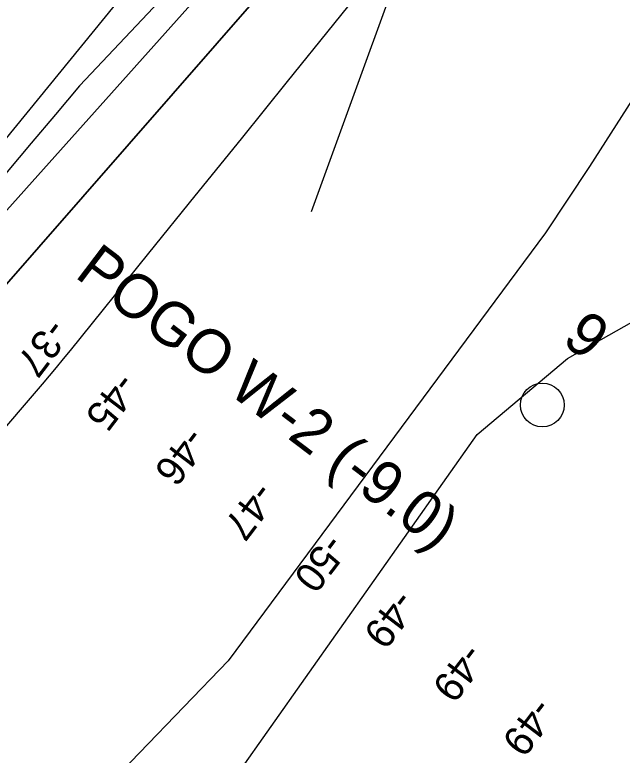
# Model space of a CAD drawing. Extents: x 3913936 to 3933962, y 195330 to 217741.
# Drawn here: x 3922257 to 3922950, y 200928 to 201772 of the extents above; entities that cross this region are included whole.
import ezdxf

# ---------------------------------------------------------------- set-up
doc = ezdxf.new("R2010")
doc.units = 0
for name, color, linetype in [('V-ANNO-TEXT', 7, 'Continuous'), ('V-CHAN-NAID', 7, 'Continuous'), ('V-RIVR-IDEN', 7, 'Continuous'), ('V-RIVR-MILE', 7, 'Continuous'), ('V-RIVR-RANG', 7, 'Continuous'), ('V-TOPO-DPTH', 7, 'Continuous'), ('V-TOPO-MAJR', 7, 'Continuous'), ('V-TOPO-MINR', 7, 'Continuous')]:
    doc.layers.add(name, color=color, linetype=linetype)

msp = doc.modelspace()

# ---------------------------------------------------------------- linework, layer by layer
at = {"layer": 'V-ANNO-TEXT'}
msp.add_lwpolyline([(3923713.15, 204620.63), (3922595.25, 201547.11)], dxfattribs=at)
at = {"layer": 'V-RIVR-MILE'}
msp.add_circle((3922858.84, 201326.88), 25, dxfattribs=at)
at = {"layer": 'V-TOPO-DPTH'}
for points in [[(3923377.96, 202699), (3922941.35, 202158.48), (3922940.31, 202157.2), (3922937.13, 202153.43), (3922933.95, 202149.66), (3922932.91, 202148.38), (3922620.43, 201761.19), (3922567.77, 201695.94), (3922515.1, 201630.7), (3922462.43, 201565.47), (3922409.75, 201500.24), (3922320.06, 201389.21), (3922312.18, 201379.53), (3922304.23, 201369.9), (3922296.21, 201360.34), (3922288.13, 201350.82), (3922167.81, 201210.31), (3922100.01, 201130.19), (3922032.83, 201049.55), (3921966.59, 200968.13), (3921900.98, 200886.2)], [(3923377.96, 202699), (3922941.35, 202158.48), (3922940.31, 202157.2), (3922937.13, 202153.43), (3922933.95, 202149.66), (3922932.91, 202148.38), (3922620.43, 201761.19), (3922567.77, 201695.94), (3922515.1, 201630.7), (3922462.43, 201565.47), (3922409.75, 201500.24), (3922320.06, 201389.21), (3922312.18, 201379.53), (3922304.23, 201369.9), (3922296.21, 201360.34), (3922288.13, 201350.82), (3922167.81, 201210.31), (3922100.01, 201130.19), (3922032.83, 201049.55), (3921966.59, 200968.13), (3921900.98, 200886.2)], [(3923095.91, 202678.46), (3922791.11, 202297.8), (3922789.59, 202295.95), (3922787.26, 202293.23), (3922784.95, 202290.48), (3922157.44, 201521.67), (3922155.7, 201519.54), (3922153.96, 201517.41), (3922152.21, 201515.29), (3922150.47, 201513.16), (3922148.07, 201510.25), (3922146.97, 201508.92), (3922146.42, 201508.26), (3922145.87, 201507.61), (3922141.95, 201502.95), (3922139.44, 201499.96), (3922136.94, 201496.96), (3922134.44, 201493.96), (3922131.96, 201490.95), (3921528.01, 200758.19)], [(3923045.56, 202377.72), (3922233.85, 201449.62), (3922231.73, 201447.13), (3922229.61, 201444.64), (3922227.46, 201442.17), (3922225.3, 201439.71), (3922161.81, 201367.9), (3922127.91, 201329.54), (3922094.02, 201291.17), (3922060.15, 201252.77), (3922026.29, 201214.37), (3921757.53, 200909.33)], [(3921757.53, 200909.33), (3922026.29, 201214.37), (3922060.15, 201252.77), (3922094.02, 201291.17), (3922127.91, 201329.54), (3922161.81, 201367.9), (3922225.3, 201439.71), (3922227.46, 201442.17), (3922229.61, 201444.64), (3922231.73, 201447.13), (3922233.85, 201449.62), (3923045.56, 202377.72)], [(3921571.56, 200731.02), (3921771, 200981.89), (3921838.64, 201066.04), (3921906.88, 201149.7), (3921976, 201232.63), (3922045.72, 201315.07), (3922153.04, 201440.58), (3922169.51, 201459.92), (3922185.93, 201479.31), (3922202.27, 201498.77), (3922970.95, 202357.51)], [(3921571.56, 200731.02), (3921771, 200981.89), (3921838.64, 201066.04), (3921906.88, 201149.7), (3921976, 201232.63), (3922045.72, 201315.07), (3922153.04, 201440.58), (3922169.51, 201459.92), (3922185.93, 201479.31), (3922202.27, 201498.77), (3922970.95, 202357.51)]]:
    msp.add_lwpolyline(points, dxfattribs=at)
at = {"layer": 'V-TOPO-MAJR'}
for points in [[(3922784.7, 201293.34), (3922887.7, 201379.88), (3923450.03, 201697.58)], [(3922961.24, 201675.14), (3922912.58, 201598.93), (3922862.65, 201523.49), (3922500.28, 201035.07)], [(3921323.53, 199362.66), (3921429.11, 199484.6), (3921440.3, 199497.41), (3921451.56, 199510.15), (3921462.94, 199522.78), (3921474.4, 199535.35), (3921526.44, 199591.94), (3921563.74, 199632.96), (3921600.74, 199674.25), (3921637.27, 199715.94), (3921673.5, 199757.91), (3922047.51, 200196.03), (3922076.19, 200231.14), (3922103.81, 200267.04), (3922129.84, 200304.1), (3922154.82, 200341.94), (3922334.63, 200627.7), (3922384.43, 200710.11), (3922432.18, 200793.65), (3922784.7, 201293.34)], [(3922500.28, 201035.07), (3922247.49, 200772.95), (3922181.56, 200701.24), (3922117.29, 200628.04), (3922054.13, 200553.84), (3921951.57, 200430.5), (3921940.66, 200417.11), (3921929.94, 200403.57)]]:
    msp.add_lwpolyline(points, dxfattribs=at)
at = {"layer": 'V-TOPO-MINR'}
for points in [[(3923377.96, 202699), (3922941.35, 202158.48), (3922940.31, 202157.2), (3922937.13, 202153.43), (3922933.95, 202149.66), (3922932.91, 202148.38), (3922620.43, 201761.19), (3922567.77, 201695.94), (3922515.1, 201630.7), (3922462.43, 201565.47), (3922409.75, 201500.24), (3922320.06, 201389.21), (3922312.18, 201379.53), (3922304.23, 201369.9), (3922296.21, 201360.34), (3922288.13, 201350.82), (3922167.81, 201210.31), (3922100.01, 201130.19), (3922032.83, 201049.55), (3921966.59, 200968.13), (3921900.98, 200886.2)], [(3923095.91, 202678.46), (3922791.11, 202297.8), (3922789.59, 202295.95), (3922787.26, 202293.23), (3922784.95, 202290.48), (3922157.44, 201521.67), (3922155.7, 201519.54), (3922153.96, 201517.41), (3922152.21, 201515.29), (3922150.47, 201513.16), (3922148.07, 201510.25), (3922146.97, 201508.92), (3922146.42, 201508.26), (3922145.87, 201507.61), (3922141.95, 201502.95), (3922139.44, 201499.96), (3922136.94, 201496.96), (3922134.44, 201493.96), (3922131.96, 201490.95), (3921528.01, 200758.19)], [(3922956.69, 202387.01), (3922940, 202360.98), (3922926.57, 202340.72), (3922912.73, 202320.75), (3922898.3, 202301.2), (3922883.47, 202281.95), (3922854.79, 202245.85), (3922330.9, 201690.94), (3922303.28, 201658.32), (3922275.74, 201625.63), (3922248.33, 201592.82), (3922221.02, 201559.94), (3922183.26, 201514.3), (3922174.87, 201504.2), (3922166.46, 201494.11), (3922158, 201484.06), (3922149.52, 201474.03), (3922091.91, 201406.13), (3922054.74, 201362.05), (3922017.74, 201317.82), (3921981.01, 201273.38), (3921944.45, 201228.79), (3921549.88, 200744.53)], [(3923045.56, 202377.72), (3922233.85, 201449.62), (3922231.73, 201447.13), (3922229.61, 201444.64), (3922227.46, 201442.17), (3922225.3, 201439.71), (3922161.81, 201367.9), (3922127.91, 201329.54), (3922094.02, 201291.17), (3922060.15, 201252.77), (3922026.29, 201214.37), (3921757.53, 200909.33)], [(3922970.95, 202357.51), (3922202.27, 201498.77), (3922185.93, 201479.31), (3922169.51, 201459.92), (3922153.04, 201440.58), (3922045.72, 201315.07), (3921976, 201232.63), (3921906.88, 201149.7), (3921838.64, 201066.04), (3921771, 200981.89), (3921571.56, 200731.02)]]:
    msp.add_lwpolyline(points, dxfattribs=at)

# ---------------------------------------------------------------- texts
at = {"layer": 'V-CHAN-NAID'}
msp.add_text('POGO W-2 (-9.0)', height=50, rotation=322.85534, dxfattribs=at).set_placement((3922324.08, 201473.75))
at = {"layer": 'V-RIVR-IDEN'}
msp.add_text('9', height=50, rotation=321.1409, dxfattribs=at).set_placement((3922879.69, 201399.1))
at = {"layer": 'V-RIVR-RANG'}
for s, p in [('-37', (3922295.99, 201427.69)), ('-45', (3922375.17, 201366.12)), ('-46', (3922454.02, 201303.79)), ('-47', (3922532.49, 201241.46)), ('-50', (3922612.94, 201182.06)), ('-49', (3922692.59, 201118.12)), ('-49', (3922771.06, 201057.11)), ('-49', (3922850.63, 200995.23))]:
    msp.add_text(s, height=33.5, rotation=232.75053, dxfattribs=at).set_placement(p)

doc.saveas('drawing.dxf')
